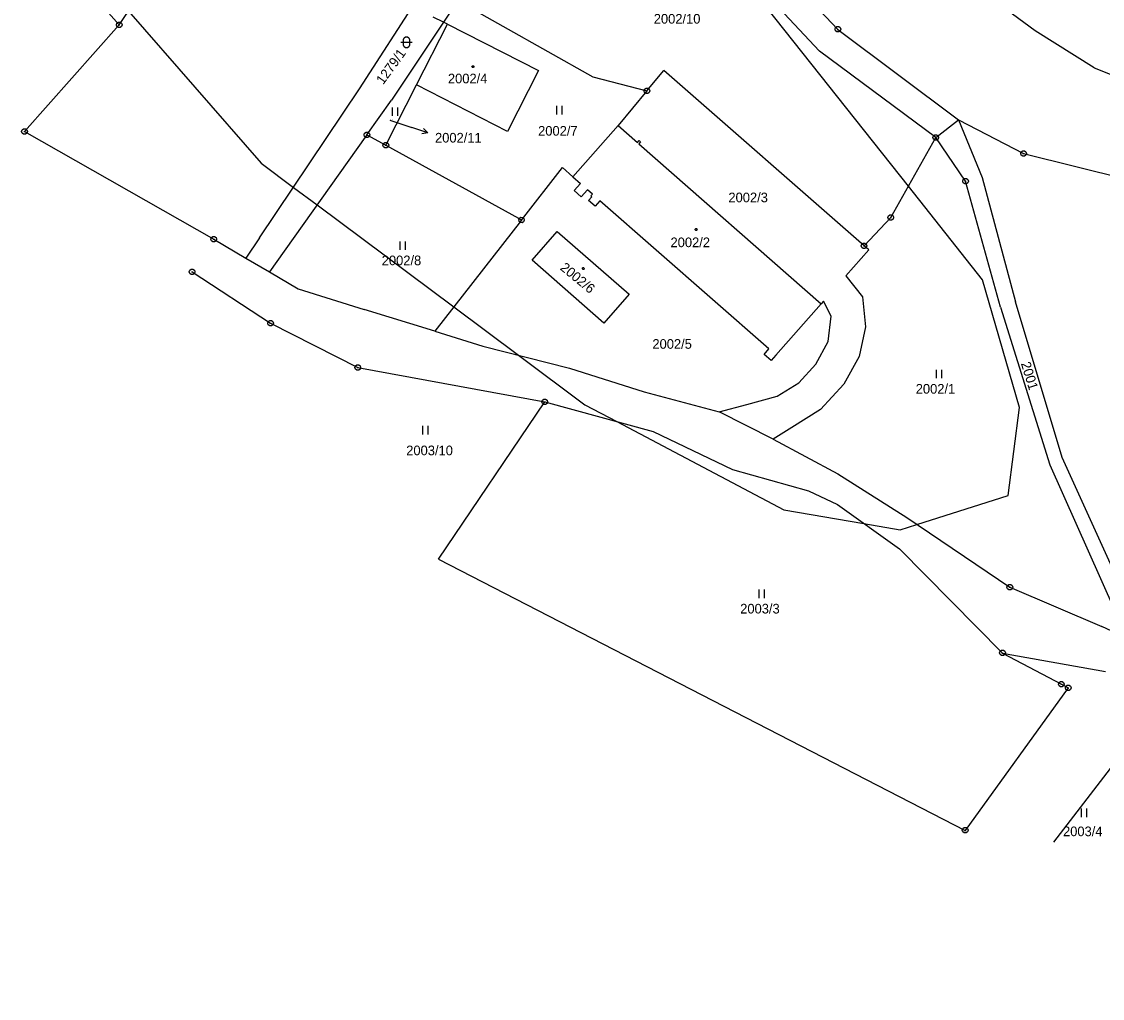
# Model space of a CAD drawing. Extents: x -806774 to -803680, y -1151731 to -1150053.
# Drawn here: x -804263.2 to -804072.9, y -1150874 to -1150702.1 of the extents above; entities that cross this region are included whole.
import ezdxf

# ---------------------------------------------------------------- set-up
doc = ezdxf.new("R2010")
doc.units = 0
for name, color, linetype in [('1', 7, 'Continuous'), ('11', 7, 'Continuous'), ('12', 7, 'Continuous'), ('2', 7, 'Continuous'), ('3', 7, 'Continuous'), ('5', 7, 'Continuous'), ('6', 7, 'Continuous'), ('7', 7, 'Continuous'), ('8', 7, 'Continuous')]:
    doc.layers.add(name, color=color, linetype=linetype)

msp = doc.modelspace()

# ---------------------------------------------------------------- linework, layer by layer
at = {"layer": '1'}
for p, q in [((-804245.97, -1150702.66), (-804230.67, -1150679.78)), ((-804135.09, -1150686.84), (-804119.46, -1150703.45)), ((-804122.73, -1150707.27), (-804138.42, -1150690.47)), ((-804203.66, -1150713.94), (-804191.87, -1150695.58)), ((-804245.97, -1150702.66), (-804249.73, -1150698.42)), ((-804186.38, -1150698.4), (-804188.91, -1150702.2)), ((-804186.38, -1150698.4), (-804162.59, -1150711.79)), ((-804245.97, -1150702.66), (-804262.66, -1150721.41)), ((-804188.91, -1150702.2), (-804198.04, -1150715.91)), ((-804193.64, -1150713.24), (-804188.2, -1150702.56)), ((-804188.91, -1150702.2), (-804190.7, -1150701.29)), ((-804188.2, -1150702.56), (-804188.91, -1150702.2)), ((-804188.2, -1150702.56), (-804172.18, -1150710.68)), ((-804119.46, -1150703.45), (-804098.25, -1150719.35)), ((-804102.23, -1150722.48), (-804122.73, -1150707.27)), ((-804172.18, -1150710.68), (-804177.63, -1150721.4)), ((-804153.08, -1150714.27), (-804150.08, -1150710.67)), ((-804114.86, -1150741.53), (-804150.08, -1150710.67)), ((-804162.59, -1150711.79), (-804153.08, -1150714.27)), ((-804221.29, -1150740.14), (-804203.66, -1150713.94)), ((-804199.04, -1150723.85), (-804193.64, -1150713.24)), ((-804177.63, -1150721.4), (-804193.64, -1150713.24)), ((-804153.08, -1150714.27), (-804158.15, -1150720.35)), ((-804202.38, -1150722.01), (-804198.04, -1150715.91)), ((-804102.23, -1150722.48), (-804098.25, -1150719.35)), ((-804098.25, -1150719.35), (-804094.06, -1150729.52)), ((-804098.25, -1150719.35), (-804086.77, -1150725.31)), ((-804262.66, -1150721.41), (-804229.34, -1150740.39)), ((-804202.38, -1150722.01), (-804216.94, -1150742.47)), ((-804202.38, -1150722.01), (-804199.04, -1150723.85)), ((-804166.11, -1150729.42), (-804158.15, -1150720.35)), ((-804158.15, -1150720.35), (-804154.73, -1150723.35)), ((-804199.04, -1150723.85), (-804175.72, -1150736.7)), ((-804154.73, -1150723.35), (-804154.44, -1150723.02)), ((-804154.19, -1150723.24), (-804154.48, -1150723.57)), ((-804154.48, -1150723.57), (-804122.41, -1150751.76)), ((-804154.44, -1150723.02), (-804154.19, -1150723.24)), ((-804110.16, -1150736.56), (-804102.23, -1150722.48)), ((-804096.98, -1150730.19), (-804102.23, -1150722.48)), ((-804086.77, -1150725.31), (-804048.58, -1150734.81)), ((-804175.17, -1150737), (-804167.95, -1150727.76)), ((-804166.11, -1150729.42), (-804167.95, -1150727.76)), ((-804166.11, -1150729.42), (-804164.8, -1150730.57)), ((-804094.06, -1150729.52), (-804088.18, -1150751.38)), ((-804165.91, -1150731.83), (-804164.8, -1150730.57)), ((-804163.53, -1150731.68), (-804164.64, -1150732.94)), ((-804162.67, -1150732.44), (-804163.53, -1150731.68)), ((-804090.85, -1150752.33), (-804096.98, -1150730.19)), ((-804164.64, -1150732.94), (-804165.91, -1150731.83)), ((-804163.34, -1150733.54), (-804162.78, -1150732.9)), ((-804162.19, -1150734.56), (-804163.34, -1150733.54)), ((-804162.95, -1150732.75), (-804162.67, -1150732.44)), ((-804162.78, -1150732.9), (-804162.95, -1150732.75)), ((-804161.35, -1150733.6), (-804162.19, -1150734.56)), ((-804131.64, -1150759.7), (-804161.35, -1150733.6)), ((-804175.17, -1150737), (-804190.43, -1150756.56)), ((-804175.72, -1150736.7), (-804175.17, -1150737)), ((-804114.86, -1150741.53), (-804110.16, -1150736.56)), ((-804173.31, -1150744.09), (-804168.86, -1150739.02)), ((-804168.86, -1150739.02), (-804156.22, -1150750.06)), ((-804229.34, -1150740.39), (-804223.69, -1150743.7)), ((-804221.29, -1150740.14), (-804223.69, -1150743.7)), ((-804216.94, -1150742.47), (-804219.54, -1150746.13)), ((-804118.04, -1150746.82), (-804114.02, -1150742.27)), ((-804114.02, -1150742.27), (-804114.86, -1150741.53)), ((-804223.69, -1150743.7), (-804219.54, -1150746.13)), ((-804160.65, -1150755.13), (-804173.31, -1150744.09)), ((-804233.16, -1150746.14), (-804219.34, -1150755.15)), ((-804219.54, -1150746.13), (-804214.5, -1150749.11)), ((-804118.04, -1150746.82), (-804115.12, -1150750.53)), ((-804214.5, -1150749.11), (-804202.85, -1150752.72)), ((-804156.22, -1150750.06), (-804160.65, -1150755.13)), ((-804115.12, -1150750.53), (-804114.63, -1150755.8)), ((-804122.41, -1150751.76), (-804130.37, -1150760.81)), ((-804122.01, -1150751.31), (-804122.41, -1150751.76)), ((-804120.67, -1150753.94), (-804122.01, -1150751.31)), ((-804090.85, -1150752.33), (-804082.13, -1150780.08)), ((-804079.95, -1150778.82), (-804088.18, -1150751.38)), ((-804190.43, -1150756.56), (-804202.85, -1150752.72)), ((-804121.17, -1150758.4), (-804120.67, -1150753.94)), ((-804219.34, -1150755.15), (-804203.98, -1150762.98)), ((-804114.63, -1150755.8), (-804115.7, -1150761.03)), ((-804190.43, -1150756.56), (-804181.96, -1150759.19)), ((-804181.96, -1150759.19), (-804166.73, -1150763.07)), ((-804132.46, -1150760.64), (-804131.64, -1150759.7)), ((-804123.35, -1150762.34), (-804121.17, -1150758.4)), ((-804131.19, -1150761.73), (-804132.46, -1150760.64)), ((-804130.37, -1150760.81), (-804131.19, -1150761.73)), ((-804115.7, -1150761.03), (-804118.39, -1150765.87)), ((-804203.98, -1150762.98), (-804171.06, -1150769.01)), ((-804166.73, -1150763.07), (-804153.59, -1150767.26)), ((-804126.33, -1150765.63), (-804123.35, -1150762.34)), ((-804130.14, -1150768.03), (-804126.33, -1150765.63)), ((-804118.39, -1150765.87), (-804122.5, -1150770.33)), ((-804153.59, -1150767.26), (-804140.34, -1150770.76)), ((-804189.77, -1150796.69), (-804171.06, -1150769.01)), ((-804171.06, -1150769.01), (-804151.98, -1150774.22)), ((-804140.34, -1150770.76), (-804135.48, -1150769.46)), ((-804135.48, -1150769.46), (-804130.14, -1150768.03)), ((-804130.88, -1150775.58), (-804140.34, -1150770.76)), ((-804122.5, -1150770.33), (-804127.59, -1150773.52)), ((-804127.59, -1150773.52), (-804130.88, -1150775.58)), ((-804151.98, -1150774.22), (-804138.04, -1150780.89)), ((-804130.88, -1150775.58), (-804119.5, -1150781.69)), ((-804068.82, -1150803.31), (-804079.95, -1150778.82)), ((-804138.04, -1150780.89), (-804124.61, -1150784.64)), ((-804082.13, -1150780.08), (-804070.81, -1150805.5)), ((-804119.5, -1150781.69), (-804107.32, -1150789.37)), ((-804124.61, -1150784.64), (-804119.54, -1150787.08)), ((-804119.54, -1150787.08), (-804108.64, -1150794.86)), ((-804107.32, -1150789.37), (-804089.19, -1150801.6)), ((-804108.64, -1150794.86), (-804090.48, -1150813.2)), ((-804189.77, -1150796.69), (-804097.05, -1150844.41)), ((-804089.19, -1150801.6), (-804073.01, -1150808.56)), ((-804068.52, -1150810.63), (-804073.01, -1150808.56)), ((-804090.48, -1150813.2), (-804072.33, -1150816.47)), ((-804090.48, -1150813.2), (-804080.12, -1150818.69)), ((-804080.12, -1150818.69), (-804078.91, -1150819.33)), ((-804078.91, -1150819.33), (-804097.05, -1150844.41))]:
    msp.add_line(p, q, dxfattribs=at)
at = {"layer": '11'}
for points in [[(-804105.55, -1150790.57), (-804089.5, -1150785.5), (-804087.5, -1150770), (-804094, -1150747.5), (-804107.05, -1150731.04), (-804147.5, -1150680)], [(-804244.36, -1150700.25), (-804221, -1150727), (-804215.31, -1150731.25), (-804211.15, -1150734.34), (-804187.09, -1150752.28), (-804175.68, -1150760.79)], [(-804175.68, -1150760.79), (-804164, -1150769.5), (-804158.37, -1150772.47), (-804129, -1150788), (-804114.87, -1150790.41), (-804108.5, -1150791.5), (-804105.55, -1150790.57)], [(-804017.05, -1150873.98), (-804020.08, -1150868.46), (-804025, -1150859.5), (-804036.28, -1150843.34), (-804043.5, -1150833), (-804055.15, -1150831.38), (-804061.5, -1150830.5), (-804071.5, -1150833.5), (-804081.5, -1150846.5)]]:
    msp.add_lwpolyline(points, dxfattribs=at)
at = {"layer": '12'}
for p, q in [((-804193.64, -1150713.24), (-804188.2, -1150702.56)), ((-804188.2, -1150702.56), (-804172.18, -1150710.68)), ((-804172.18, -1150710.68), (-804177.63, -1150721.4)), ((-804177.63, -1150721.4), (-804193.64, -1150713.24)), ((-804166.11, -1150729.42), (-804158.15, -1150720.35)), ((-804158.15, -1150720.35), (-804154.73, -1150723.35)), ((-804154.73, -1150723.35), (-804154.44, -1150723.02)), ((-804154.19, -1150723.24), (-804154.48, -1150723.57)), ((-804154.48, -1150723.57), (-804122.41, -1150751.76)), ((-804154.44, -1150723.02), (-804154.19, -1150723.24)), ((-804166.11, -1150729.42), (-804164.8, -1150730.57)), ((-804165.91, -1150731.83), (-804164.8, -1150730.57)), ((-804163.53, -1150731.68), (-804164.64, -1150732.94)), ((-804162.67, -1150732.44), (-804163.53, -1150731.68)), ((-804164.64, -1150732.94), (-804165.91, -1150731.83)), ((-804163.34, -1150733.54), (-804162.78, -1150732.9)), ((-804162.19, -1150734.56), (-804163.34, -1150733.54)), ((-804162.95, -1150732.75), (-804162.67, -1150732.44)), ((-804162.78, -1150732.9), (-804162.95, -1150732.75)), ((-804161.35, -1150733.6), (-804162.19, -1150734.56)), ((-804131.64, -1150759.7), (-804161.35, -1150733.6)), ((-804173.31, -1150744.09), (-804168.86, -1150739.02)), ((-804168.86, -1150739.02), (-804156.22, -1150750.06)), ((-804160.65, -1150755.13), (-804173.31, -1150744.09)), ((-804156.22, -1150750.06), (-804160.65, -1150755.13)), ((-804122.41, -1150751.76), (-804130.37, -1150760.81)), ((-804132.46, -1150760.64), (-804131.64, -1150759.7)), ((-804131.19, -1150761.73), (-804132.46, -1150760.64)), ((-804130.37, -1150760.81), (-804131.19, -1150761.73))]:
    msp.add_line(p, q, dxfattribs=at)
at = {"layer": '3'}
for p, q in [((-804197.93, -1150717.19), (-804197.93, -1150718.69)), ((-804196.93, -1150718.69), (-804196.93, -1150717.19)), ((-804169.02, -1150716.92), (-804169.02, -1150718.42)), ((-804168.02, -1150718.42), (-804168.02, -1150716.92)), ((-804196.57, -1150740.76), (-804196.57, -1150742.26)), ((-804195.57, -1150742.26), (-804195.57, -1150740.76)), ((-804102.18, -1150763.36), (-804102.18, -1150764.86)), ((-804101.18, -1150764.86), (-804101.18, -1150763.36)), ((-804192.59, -1150773.24), (-804192.59, -1150774.74)), ((-804191.59, -1150774.74), (-804191.59, -1150773.24)), ((-804133.4, -1150802.05), (-804133.4, -1150803.55)), ((-804132.4, -1150803.55), (-804132.4, -1150802.05)), ((-804076.64, -1150840.59), (-804076.64, -1150842.09)), ((-804075.64, -1150842.09), (-804075.64, -1150840.59))]:
    msp.add_line(p, q, dxfattribs=at)
msp.add_lwpolyline([(-804195.92, -1150705.22), (-804195.82, -1150704.93), (-804195.57, -1150704.75), (-804195.26, -1150704.75), (-804195.01, -1150704.93), (-804194.91, -1150705.22), (-804194.91, -1150706.22), (-804195.01, -1150706.51), (-804195.26, -1150706.69), (-804195.57, -1150706.69), (-804195.82, -1150706.51), (-804195.92, -1150706.22)], close=True, dxfattribs=at)
msp.add_lwpolyline([(-804196.42, -1150705.72), (-804195.15, -1150705.72), (-804194.42, -1150705.72)], dxfattribs=at)
at = {"layer": '5'}
for points in [[(-804183.72, -1150709.84), (-804183.62, -1150709.86), (-804183.57, -1150709.95), (-804183.55, -1150710.01), (-804183.57, -1150710.1), (-804183.65, -1150710.17), (-804183.72, -1150710.18), (-804183.81, -1150710.15), (-804183.87, -1150710.09), (-804183.89, -1150710.01), (-804183.87, -1150709.92), (-804183.79, -1150709.85)], [(-804144.32, -1150738.55), (-804144.26, -1150738.64), (-804144.28, -1150738.74), (-804144.3, -1150738.79), (-804144.38, -1150738.85), (-804144.49, -1150738.85), (-804144.54, -1150738.81), (-804144.59, -1150738.72), (-804144.59, -1150738.64), (-804144.56, -1150738.57), (-804144.48, -1150738.51), (-804144.37, -1150738.51)], [(-804164.17, -1150745.42), (-804164.11, -1150745.51), (-804164.13, -1150745.61), (-804164.15, -1150745.66), (-804164.23, -1150745.72), (-804164.34, -1150745.72), (-804164.39, -1150745.68), (-804164.44, -1150745.59), (-804164.44, -1150745.51), (-804164.41, -1150745.44), (-804164.33, -1150745.38), (-804164.22, -1150745.38)]]:
    msp.add_lwpolyline(points, close=True, dxfattribs=at)
at = {"layer": '6'}
for p, q in [((-804084.74, -1150703.71), (-804103.55, -1150689.77)), ((-804074.35, -1150710.2), (-804084.74, -1150703.71)), ((-804074.35, -1150710.2), (-804063.34, -1150714.6))]:
    msp.add_line(p, q, dxfattribs=at)
at = {"layer": '7'}
for p in [(-804198.35, -1150719.41), (-804191.63, -1150721.67)]:
    msp.add_line(p, (-804194.47, -1150720.71), dxfattribs=at)
msp.add_lwpolyline([(-804192.41, -1150720.87), (-804191.63, -1150721.67), (-804192.73, -1150721.82)], dxfattribs=at)
at = {"layer": '8'}
for p, q in [((-804246.09, -1150702.66), (-804245.85, -1150702.66)), ((-804119.58, -1150703.45), (-804119.34, -1150703.45)), ((-804153.2, -1150714.27), (-804152.96, -1150714.27)), ((-804262.78, -1150721.41), (-804262.54, -1150721.41)), ((-804202.5, -1150722.01), (-804202.26, -1150722.01)), ((-804199.16, -1150723.85), (-804198.92, -1150723.85)), ((-804102.35, -1150722.48), (-804102.11, -1150722.48)), ((-804086.89, -1150725.31), (-804086.65, -1150725.31)), ((-804097.1, -1150730.19), (-804096.86, -1150730.19)), ((-804175.26, -1150736.92), (-804175.08, -1150737.08)), ((-804110.28, -1150736.56), (-804110.04, -1150736.56)), ((-804229.46, -1150740.39), (-804229.22, -1150740.39)), ((-804114.98, -1150741.53), (-804114.74, -1150741.53)), ((-804233.28, -1150746.14), (-804233.04, -1150746.14)), ((-804219.46, -1150755.15), (-804219.22, -1150755.15)), ((-804204.1, -1150762.98), (-804203.86, -1150762.98)), ((-804171.18, -1150769.01), (-804170.94, -1150769.01)), ((-804089.31, -1150801.6), (-804089.07, -1150801.6)), ((-804090.6, -1150813.2), (-804090.36, -1150813.2)), ((-804080.24, -1150818.69), (-804080, -1150818.69)), ((-804079.03, -1150819.33), (-804078.79, -1150819.33)), ((-804097.17, -1150844.41), (-804096.93, -1150844.41))]:
    msp.add_line(p, q, dxfattribs=at)
for points in [[(-804245.82, -1150702.18), (-804245.57, -1150702.36), (-804245.47, -1150702.65), (-804245.57, -1150702.94), (-804245.82, -1150703.12), (-804246.13, -1150703.12), (-804246.38, -1150702.94), (-804246.48, -1150702.65), (-804246.38, -1150702.36), (-804246.13, -1150702.18)], [(-804119.31, -1150702.97), (-804119.06, -1150703.15), (-804118.96, -1150703.44), (-804119.06, -1150703.73), (-804119.31, -1150703.91), (-804119.62, -1150703.91), (-804119.87, -1150703.73), (-804119.97, -1150703.44), (-804119.87, -1150703.15), (-804119.62, -1150702.97)], [(-804152.93, -1150713.79), (-804152.68, -1150713.97), (-804152.58, -1150714.26), (-804152.68, -1150714.55), (-804152.93, -1150714.73), (-804153.24, -1150714.73), (-804153.49, -1150714.55), (-804153.59, -1150714.26), (-804153.49, -1150713.97), (-804153.24, -1150713.79)], [(-804262.51, -1150720.93), (-804262.26, -1150721.11), (-804262.16, -1150721.4), (-804262.26, -1150721.69), (-804262.51, -1150721.87), (-804262.82, -1150721.87), (-804263.07, -1150721.69), (-804263.17, -1150721.4), (-804263.07, -1150721.11), (-804262.82, -1150720.93)], [(-804202.23, -1150721.53), (-804201.98, -1150721.71), (-804201.88, -1150722), (-804201.98, -1150722.29), (-804202.23, -1150722.47), (-804202.54, -1150722.47), (-804202.79, -1150722.29), (-804202.89, -1150722), (-804202.79, -1150721.71), (-804202.54, -1150721.53)], [(-804102.08, -1150722), (-804101.83, -1150722.18), (-804101.73, -1150722.47), (-804101.83, -1150722.76), (-804102.08, -1150722.94), (-804102.39, -1150722.94), (-804102.64, -1150722.76), (-804102.74, -1150722.47), (-804102.64, -1150722.18), (-804102.39, -1150722)], [(-804198.89, -1150723.37), (-804198.64, -1150723.55), (-804198.54, -1150723.84), (-804198.64, -1150724.13), (-804198.89, -1150724.31), (-804199.2, -1150724.31), (-804199.45, -1150724.13), (-804199.55, -1150723.84), (-804199.45, -1150723.55), (-804199.2, -1150723.37)], [(-804086.62, -1150724.83), (-804086.37, -1150725.01), (-804086.27, -1150725.3), (-804086.37, -1150725.59), (-804086.62, -1150725.77), (-804086.93, -1150725.77), (-804087.18, -1150725.59), (-804087.28, -1150725.3), (-804087.18, -1150725.01), (-804086.93, -1150724.83)], [(-804096.83, -1150729.71), (-804096.58, -1150729.89), (-804096.48, -1150730.18), (-804096.58, -1150730.47), (-804096.83, -1150730.65), (-804097.14, -1150730.65), (-804097.39, -1150730.47), (-804097.49, -1150730.18), (-804097.39, -1150729.89), (-804097.14, -1150729.71)], [(-804174.74, -1150736.75), (-804174.67, -1150737.05), (-804174.79, -1150737.33), (-804175.06, -1150737.48), (-804175.37, -1150737.44), (-804175.6, -1150737.23), (-804175.66, -1150736.93), (-804175.54, -1150736.65), (-804175.27, -1150736.5), (-804174.97, -1150736.54)], [(-804110.01, -1150736.08), (-804109.76, -1150736.26), (-804109.66, -1150736.55), (-804109.76, -1150736.84), (-804110.01, -1150737.02), (-804110.32, -1150737.02), (-804110.57, -1150736.84), (-804110.67, -1150736.55), (-804110.57, -1150736.26), (-804110.32, -1150736.08)], [(-804229.19, -1150739.91), (-804228.94, -1150740.09), (-804228.84, -1150740.38), (-804228.94, -1150740.67), (-804229.19, -1150740.85), (-804229.5, -1150740.85), (-804229.75, -1150740.67), (-804229.85, -1150740.38), (-804229.75, -1150740.09), (-804229.5, -1150739.91)], [(-804114.71, -1150741.05), (-804114.46, -1150741.23), (-804114.36, -1150741.52), (-804114.46, -1150741.81), (-804114.71, -1150741.99), (-804115.02, -1150741.99), (-804115.27, -1150741.81), (-804115.37, -1150741.52), (-804115.27, -1150741.23), (-804115.02, -1150741.05)], [(-804233.01, -1150745.66), (-804232.76, -1150745.84), (-804232.66, -1150746.13), (-804232.76, -1150746.42), (-804233.01, -1150746.6), (-804233.32, -1150746.6), (-804233.57, -1150746.42), (-804233.67, -1150746.13), (-804233.57, -1150745.84), (-804233.32, -1150745.66)], [(-804219.19, -1150754.67), (-804218.94, -1150754.85), (-804218.84, -1150755.14), (-804218.94, -1150755.43), (-804219.19, -1150755.61), (-804219.5, -1150755.61), (-804219.75, -1150755.43), (-804219.85, -1150755.14), (-804219.75, -1150754.85), (-804219.5, -1150754.67)], [(-804203.83, -1150762.5), (-804203.58, -1150762.68), (-804203.48, -1150762.97), (-804203.58, -1150763.26), (-804203.83, -1150763.44), (-804204.14, -1150763.44), (-804204.39, -1150763.26), (-804204.49, -1150762.97), (-804204.39, -1150762.68), (-804204.14, -1150762.5)], [(-804170.91, -1150768.53), (-804170.66, -1150768.71), (-804170.56, -1150769), (-804170.66, -1150769.29), (-804170.91, -1150769.47), (-804171.22, -1150769.47), (-804171.47, -1150769.29), (-804171.57, -1150769), (-804171.47, -1150768.71), (-804171.22, -1150768.53)], [(-804089.04, -1150801.12), (-804088.79, -1150801.3), (-804088.69, -1150801.59), (-804088.79, -1150801.88), (-804089.04, -1150802.06), (-804089.35, -1150802.06), (-804089.6, -1150801.88), (-804089.7, -1150801.59), (-804089.6, -1150801.3), (-804089.35, -1150801.12)], [(-804090.33, -1150812.72), (-804090.08, -1150812.9), (-804089.98, -1150813.19), (-804090.08, -1150813.48), (-804090.33, -1150813.66), (-804090.64, -1150813.66), (-804090.89, -1150813.48), (-804090.99, -1150813.19), (-804090.89, -1150812.9), (-804090.64, -1150812.72)], [(-804079.97, -1150818.21), (-804079.72, -1150818.39), (-804079.62, -1150818.68), (-804079.72, -1150818.97), (-804079.97, -1150819.15), (-804080.28, -1150819.15), (-804080.53, -1150818.97), (-804080.63, -1150818.68), (-804080.53, -1150818.39), (-804080.28, -1150818.21)], [(-804078.76, -1150818.85), (-804078.51, -1150819.03), (-804078.41, -1150819.32), (-804078.51, -1150819.61), (-804078.76, -1150819.79), (-804079.07, -1150819.79), (-804079.32, -1150819.61), (-804079.42, -1150819.32), (-804079.32, -1150819.03), (-804079.07, -1150818.85)], [(-804096.9, -1150843.93), (-804096.65, -1150844.11), (-804096.55, -1150844.4), (-804096.65, -1150844.69), (-804096.9, -1150844.87), (-804097.21, -1150844.87), (-804097.46, -1150844.69), (-804097.56, -1150844.4), (-804097.46, -1150844.11), (-804097.21, -1150843.93)]]:
    msp.add_lwpolyline(points, close=True, dxfattribs=at)

# ---------------------------------------------------------------- texts
at = {"layer": '2'}
for s, height, p in [('2002/10', 1.7, (-804151.88, -1150702.44)), ('2002/4', 1.7, (-804188.12, -1150712.95)), ('2002/11', 0.1, (-804198.34, -1150719.41)), ('2002/7', 1.7, (-804172.24, -1150722.16)), ('2002/3', 1.7, (-804138.74, -1150733.88)), ('2002/2', 1.7, (-804148.93, -1150741.78)), ('2002/8', 1.7, (-804199.77, -1150744.96)), ('2002/5', 1.7, (-804152.12, -1150759.66)), ('2002/1', 1.7, (-804105.76, -1150767.56)), ('2003/10', 1.7, (-804195.46, -1150778.4)), ('2003/3', 1.7, (-804136.66, -1150806.25)), ('2003/4', 1.7, (-804079.83, -1150845.44))]:
    msp.add_text(s, height=height, dxfattribs=at).set_placement(p)
for s, rotation, p in [('1279/1', 53.9726, (-804199.52, -1150713.28)), ('2002/6', 320.5699, (-804168.49, -1150745.63)), ('2001', 287.1092, (-804087.26, -1150762.24))]:
    msp.add_text(s, height=1.7, rotation=rotation, dxfattribs=at).set_placement(p)
at = {"layer": '7'}
msp.add_text('2002/11', height=1.7, dxfattribs=at).set_placement((-804190.39, -1150723.37))

doc.saveas('drawing.dxf')
